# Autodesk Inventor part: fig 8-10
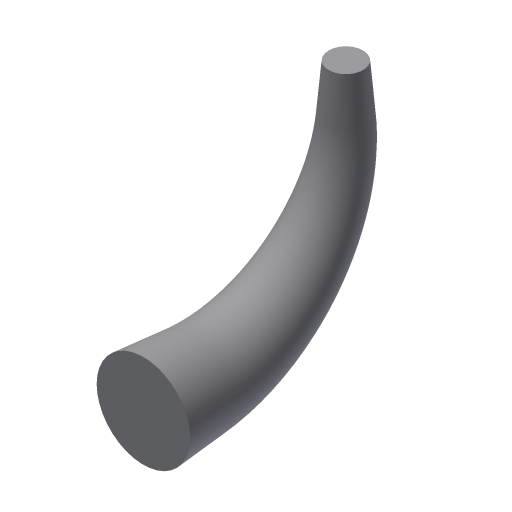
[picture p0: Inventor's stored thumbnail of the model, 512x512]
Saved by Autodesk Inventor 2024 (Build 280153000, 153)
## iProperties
Shininess: 77.0
Length Units: 11269
Angle Units: 11279
Time Units: 11290
Mass Units: 11283
Length Display Precision: 3
Angle Display Precision: 2
Created: 2001-12
Part Number: fig 8-10
Document SubType Name: Modeling
Designer: CADSoft
Density: 1 g/cm^3
Material: Generic
Appearance: Default
Density: 0.0
Volumn: 0.0
Area: 0.0
PropertySet Name: Model Information
Control State: 0
Master: False
Checked Out: False
Author: CADSoft
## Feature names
1. Sweep7
## Parameters: d4 = 15 mm, d5 = 15 mm, d13 = -5 deg, d14 = 0
